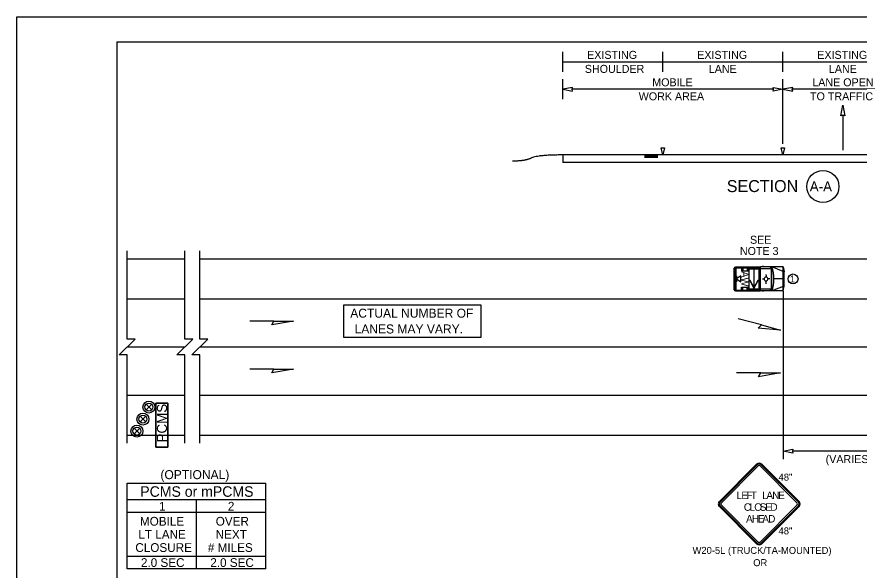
# Model space of a CAD drawing. Extents: x 0 to 17, y 0 to 11.
# Drawn here: x 0 to 8.42, y 5.47 to 11 of the extents above; entities that cross this region are included whole.
import ezdxf

# ---------------------------------------------------------------- set-up
doc = ezdxf.new("R2010")
doc.units = 0
for name, color, linetype in [('RD_ED_ShoulderPavedEdge', 7, 'Continuous'), ('RD_MK_LineEdgeWhite', 7, 'Continuous'), ('RD_MK_LineEdgeYellow', 7, 'Continuous'), ('RD_MK_LineLane', 7, 'Continuous'), ('SH_GI_PlotLimits', 7, 'Continuous'), ('SH_GI_SheetBorder3', 7, 'Continuous'), ('SH_TI_Tables', 7, 'Continuous'), ('SH_TI_WZSectionCut', 7, 'Continuous'), ('TR_SN_ConstructionSigns', 7, 'Continuous'), ('TR_WZ_ArrowLeftStrRightTurn', 7, 'Continuous'), ('TR_WZ_PCMS', 7, 'Continuous'), ('TR_WZ_PortableChangeMessageSign', 7, 'Continuous'), ('TR_WZ_PortableSignMountBlk-Org', 7, 'Continuous'), ('TR_WZ_ProtectiveVehicle', 7, 'Continuous'), ('TR_WZ_TrafficSafetyDrum', 7, 'Continuous'), ('TR_WZ_TransportableAttenuator', 7, 'Continuous'), ('TR_WZ_WorkZoneDetails', 7, 'Continuous'), ('TR_WZ_WorkZoneTextCurrent', 7, 'Continuous')]:
    doc.layers.add(name, color=color, linetype=linetype)

msp = doc.modelspace()

# ---------------------------------------------------------------- linework, layer by layer
at = {"layer": 'RD_ED_ShoulderPavedEdge'}
for p, q in [((1.1016, 8.5807), (1.6783, 8.5807)), ((1.8283, 8.5807), (16.62, 8.5807)), ((1.1016, 6.8207), (1.6783, 6.8207)), ((1.8283, 6.8207), (16.62, 6.8207))]:
    msp.add_line(p, q, dxfattribs=at)
at = {"layer": 'RD_MK_LineEdgeWhite'}
for p, q in [((1.1016, 7.2207), (1.6783, 7.2207)), ((1.8283, 7.2207), (16.62, 7.2207))]:
    msp.add_line(p, q, dxfattribs=at)
at = {"layer": 'RD_MK_LineEdgeYellow'}
for p, q in [((1.1016, 8.1807), (1.6783, 8.1807)), ((1.8283, 8.1807), (16.62, 8.1807))]:
    msp.add_line(p, q, dxfattribs=at)
at = {"layer": 'RD_MK_LineLane'}
for p, q in [((1.6783, 7.7007), (1.1016, 7.7007)), ((16.62, 7.7007), (1.8283, 7.7007))]:
    msp.add_line(p, q, dxfattribs=at)
at = {"layer": 'SH_GI_PlotLimits'}
msp.add_lwpolyline([(0, 11), (17, 11), (17, 0), (0, 0)], close=True, dxfattribs=at)
at = {"layer": 'SH_GI_SheetBorder3'}
for q in [(16.75, 10.75), (1, 0.25)]:
    msp.add_line((1, 10.75), q, dxfattribs=at)
at = {"layer": 'SH_TI_Tables'}
msp.add_lwpolyline([(3.266, 8.1232), (4.6358, 8.1232), (4.6358, 7.7968), (3.266, 7.7968)], close=True, dxfattribs=at)
at = {"layer": 'SH_TI_WZSectionCut'}
for p, q in [((5.4546, 10.45), (5.4546, 10.65)), ((6.4546, 10.45), (6.4546, 10.65)), ((7.6546, 10.45), (7.6546, 10.65)), ((5.4546, 10.55), (6.4546, 10.55)), ((6.4546, 10.55), (7.6546, 10.55)), ((7.6546, 10.55), (8.8546, 10.55)), ((5.4546, 10.176), (5.4546, 10.376)), ((7.6546, 9.7297), (7.6546, 10.376)), ((7.5609, 10.276), (5.5484, 10.276)), ((8.7609, 10.276), (7.7484, 10.276)), ((5.4546, 9.6199), (5.4546, 9.5449)), ((9.8546, 9.6199), (5.4546, 9.6199)), ((6.2716, 9.6147), (6.4046, 9.6147)), ((6.2716, 9.6091), (6.4046, 9.6091)), ((6.2716, 9.6034), (6.4046, 9.6034)), ((6.2716, 9.5982), (6.4046, 9.5982)), ((9.8546, 9.5449), (5.4546, 9.5449))]:
    msp.add_line(p, q, dxfattribs=at)
for points in [[(5.4546, 10.276), (5.5529, 10.2567), (5.5484, 10.276), (5.5529, 10.2953)], [(7.6546, 10.276), (7.5564, 10.2567), (7.5609, 10.276), (7.5564, 10.2953)], [(7.6546, 10.276), (7.7529, 10.2567), (7.7484, 10.276), (7.7529, 10.2953)], [(6.4379, 9.6897), (6.4713, 9.6897), (6.4546, 9.6199)], [(7.638, 9.6897), (7.6713, 9.6897), (7.6547, 9.6199)]]:
    msp.add_lwpolyline(points, close=True, dxfattribs=at)
msp.add_circle((8.055, 9.305), 0.16, dxfattribs=at)
msp.add_open_spline([(5.4546, 9.6199), (5.2035, 9.6199), (5.078, 9.5578), (4.9525, 9.5578)], degree=2, dxfattribs=at)
at = {"layer": 'TR_SN_ConstructionSigns'}
for p, q in [((7.3917, 6.5301), (7.0205, 6.1588)), ((7.3984, 6.5234), (7.0271, 6.1522)), ((7.0382, 6.1411), (7.4094, 6.5124)), ((7.4271, 6.5124), (7.7983, 6.1411)), ((7.8094, 6.1522), (7.4381, 6.5234)), ((7.816, 6.1588), (7.4448, 6.5301)), ((7.0205, 6.1058), (7.3917, 5.7345)), ((7.0271, 6.1124), (7.3984, 5.7412)), ((7.4094, 5.7522), (7.0382, 6.1235)), ((7.7983, 6.1235), (7.4271, 5.7522)), ((7.4381, 5.7412), (7.8094, 6.1124)), ((7.4448, 5.7345), (7.816, 6.1058))]:
    msp.add_line(p, q, dxfattribs=at)
for centre, radius, start, end in [((7.4183, 6.5036), 0.0375, 45, 135), ((7.4183, 6.5036), 0.0281, 45, 135), ((7.4183, 6.5036), 0.0125, 45, 135), ((7.047, 6.1323), 0.0375, 135, 225.00001), ((7.047, 6.1323), 0.0281, 135, 225.00001), ((7.7895, 6.1323), 0.0281, 315.00002, 45), ((7.7895, 6.1323), 0.0375, 315.00001, 45.00001), ((7.047, 6.1323), 0.0125, 135, 225.00001), ((7.7895, 6.1323), 0.0125, 315.00002, 45), ((7.4183, 5.7611), 0.0375, 225.00001, 315.00001), ((7.4183, 5.7611), 0.0281, 225.00001, 315.00002), ((7.4183, 5.7611), 0.0125, 225.00001, 315.00002)]:
    msp.add_arc(centre, radius, start, end, dxfattribs=at)
at = {"layer": 'TR_WZ_ArrowLeftStrRightTurn'}
msp.add_line((8.2546, 10.0168), (8.2546, 9.667), dxfattribs=at)
msp.add_lwpolyline([(8.2546, 10.117), (8.2752, 10.0119), (8.2546, 10.0168), (8.234, 10.0119)], close=True, dxfattribs=at)
at = {"layer": 'TR_WZ_PCMS'}
for points in [[(1.39, 7.1407), (1.51, 7.1407), (1.51, 6.7007), (1.39, 6.7007), (1.39, 7.1407)], [(1.39, 6.7007), (1.51, 6.7007), (1.51, 7.1407), (1.39, 7.1407), (1.39, 6.7007)]]:
    msp.add_lwpolyline(points, dxfattribs=at)
at = {"layer": 'TR_WZ_PortableChangeMessageSign'}
for p, q in [((1.1016, 6.3407), (2.4876, 6.3407)), ((1.1016, 5.4839), (1.1016, 6.3407)), ((2.4876, 5.4839), (2.4876, 6.3407)), ((2.4876, 6.1727), (1.1016, 6.1727)), ((1.7946, 5.4839), (1.7946, 6.1727)), ((1.7946, 6.0467), (1.1016, 6.0467)), ((2.4876, 6.0467), (1.7946, 6.0467)), ((1.1016, 5.6099), (1.7946, 5.6099)), ((1.7946, 5.6099), (2.4876, 5.6099)), ((2.4876, 5.4839), (1.1016, 5.4839))]:
    msp.add_line(p, q, dxfattribs=at)
at = {"layer": 'TR_WZ_PortableSignMountBlk-Org'}
msp.add_line((7.1919, 8.4107), (7.1919, 8.3507), dxfattribs=at)
msp.add_lwpolyline([(7.1919, 8.3807), (7.235, 8.3507), (7.235, 8.4107)], close=True, dxfattribs=at)
at = {"layer": 'TR_WZ_ProtectiveVehicle'}
for p, q in [((7.4611, 8.5041), (7.4475, 8.5041)), ((7.1685, 8.272), (7.1685, 8.4895)), ((7.1739, 8.4968), (7.1792, 8.4968)), ((7.1792, 8.2647), (7.1792, 8.4968)), ((7.18, 8.5007), (7.4269, 8.5007)), ((7.18, 8.2607), (7.18, 8.5007)), ((7.187, 8.2703), (7.187, 8.4912)), ((7.187, 8.4912), (7.4199, 8.4912)), ((7.2427, 8.4912), (7.2427, 8.4635)), ((7.2427, 8.4635), (7.3086, 8.4635)), ((7.2559, 8.4912), (7.2559, 8.4635)), ((7.2967, 8.4912), (7.2967, 8.4635)), ((7.3086, 8.4912), (7.3086, 8.4635)), ((7.4199, 8.2703), (7.4199, 8.4912)), ((7.4269, 8.2607), (7.4269, 8.5007)), ((7.4302, 8.2607), (7.4302, 8.5007)), ((7.6569, 8.5007), (7.4302, 8.5007)), ((7.5415, 8.4821), (7.4302, 8.4821)), ((7.4862, 8.4269), (7.4866, 8.4088)), ((7.5295, 8.4821), (7.5415, 8.5007)), ((7.5415, 8.2607), (7.5415, 8.5007)), ((7.5435, 8.2607), (7.5435, 8.5007)), ((7.6569, 8.4568), (7.5435, 8.5007)), ((7.6569, 8.2607), (7.6569, 8.5007)), ((7.6569, 8.5007), (7.668, 8.4523)), ((7.668, 8.3092), (7.668, 8.4523)), ((7.1685, 8.3976), (7.1792, 8.3931)), ((7.1685, 8.3638), (7.1792, 8.3683)), ((7.1714, 8.3807), (7.1763, 8.3807)), ((7.1739, 8.3773), (7.1739, 8.3841)), ((7.4501, 8.3816), (7.4679, 8.3812)), ((7.4702, 8.3811), (7.4702, 8.3811)), ((7.4871, 8.3332), (7.4871, 8.3525)), ((7.5233, 8.3806), (7.5081, 8.3806)), ((7.6569, 8.3807), (7.5658, 8.3807)), ((7.1739, 8.2647), (7.1792, 8.2647)), ((7.18, 8.2607), (7.4269, 8.2607)), ((7.187, 8.2703), (7.4199, 8.2703)), ((7.2427, 8.2979), (7.3086, 8.2979)), ((7.2427, 8.2703), (7.2427, 8.2979)), ((7.2559, 8.2703), (7.2559, 8.2979)), ((7.2967, 8.2703), (7.2967, 8.2979)), ((7.3086, 8.2703), (7.3086, 8.2979)), ((7.5415, 8.2793), (7.4302, 8.2793)), ((7.6569, 8.2607), (7.4302, 8.2607)), ((7.4611, 8.2573), (7.4475, 8.2573)), ((7.5415, 8.2607), (7.5271, 8.2793)), ((7.6569, 8.3047), (7.5435, 8.2607)), ((7.6569, 8.2607), (7.668, 8.3092))]:
    msp.add_line(p, q, dxfattribs=at)
for centre, major_axis, start_param, end_param in [((7.1739, 8.4895), (0, 0.00732), 0, 1.570796), ((7.3816, 8.3808), (0, 0.2518), 4.215667, 5.208926), ((7.1739, 8.272), (0, -0.00732), 4.712389, 6.283185)]:
    msp.add_ellipse(centre, major_axis=major_axis, ratio=0.73155, start_param=start_param, end_param=end_param, dxfattribs=at)
for centre, major_axis in [((7.1739, 8.3807), (0, -0.00338)), ((7.4871, 8.3807), (0, -0.0231))]:
    msp.add_ellipse(centre, major_axis=major_axis, ratio=0.73155, dxfattribs=at)
at = {"layer": 'TR_WZ_TrafficSafetyDrum'}
for p, q in [((1.2917, 7.129), (1.3483, 7.0724)), ((1.3483, 7.129), (1.2917, 7.0724)), ((1.2317, 7.009), (1.2883, 6.9524)), ((1.2883, 7.009), (1.2317, 6.9524)), ((1.1717, 6.889), (1.2283, 6.8324)), ((1.2283, 6.889), (1.1717, 6.8324))]:
    msp.add_line(p, q, dxfattribs=at)
for centre, radius in [((1.32, 7.1007), 0.06), ((1.32, 7.1007), 0.06), ((1.32, 7.1007), 0.04), ((1.26, 6.9807), 0.06), ((1.26, 6.9807), 0.06), ((1.26, 6.9807), 0.04), ((1.2, 6.8607), 0.06), ((1.2, 6.8607), 0.06), ((1.2, 6.8607), 0.04)]:
    msp.add_circle(centre, radius, dxfattribs=at)
at = {"layer": 'TR_WZ_TransportableAttenuator'}
for points in [[(7.3173, 8.4825), (7.4133, 8.4825), (7.4133, 8.2789), (7.3173, 8.2789)], [(7.3637, 8.4743), (7.3637, 8.2973), (7.3669, 8.2973), (7.3669, 8.4743)], [(7.3239, 8.3646), (7.3653, 8.2871), (7.3637, 8.2973), (7.3266, 8.3669)], [(7.3653, 8.2871), (7.4066, 8.3646), (7.4039, 8.3669), (7.3669, 8.2973)], [(7.3653, 8.2871), (7.3669, 8.2973), (7.3637, 8.2973)]]:
    msp.add_lwpolyline(points, close=True, dxfattribs=at)
at = {"layer": 'TR_WZ_WorkZoneDetails'}
for p, q in [((7.6569, 8.2607), (7.6569, 6.5811)), ((2.5694, 7.96), (2.3283, 7.96)), ((7.4398, 7.9214), (7.2069, 7.9838)), ((2.5694, 7.48), (2.3283, 7.48)), ((7.4331, 7.4414), (7.192, 7.4414)), ((9.5632, 6.6611), (7.7506, 6.6611))]:
    msp.add_line(p, q, dxfattribs=at)
for points in [[(1.1016, 6.7407), (1.1016, 7.6233), (1.0216, 7.6233), (1.1817, 7.7782), (1.1016, 7.7782), (1.1016, 8.6607)], [(1.6783, 6.7407), (1.6783, 7.6233), (1.5983, 7.6233), (1.7583, 7.7782), (1.6783, 7.7782), (1.6783, 8.6607)], [(1.8283, 6.7407), (1.8283, 7.6233), (1.7483, 7.6233), (1.9083, 7.7782), (1.8283, 7.7782), (1.8283, 8.6607)]]:
    msp.add_lwpolyline(points, dxfattribs=at)
for points in [[(2.766, 7.96), (2.5471, 7.9214), (2.5694, 7.96)], [(7.6296, 7.8706), (7.4083, 7.89), (7.4398, 7.9214)], [(2.766, 7.48), (2.5471, 7.4414), (2.5694, 7.48)], [(7.6296, 7.4414), (7.4108, 7.4029), (7.4331, 7.4414)], [(7.6569, 6.6611), (7.7552, 6.6803), (7.7506, 6.6611), (7.7552, 6.6418)]]:
    msp.add_lwpolyline(points, close=True, dxfattribs=at)
msp.add_circle((7.7561, 8.3807), 0.05, dxfattribs=at)

# ---------------------------------------------------------------- texts
at = {"layer": 'SH_TI_Tables'}
for s, p in [('ACTUAL NUMBER OF', (3.3317, 7.9938)), ('LANES MAY VARY.', (3.375, 7.8363))]:
    msp.add_text(s, height=0.09, rotation=360, dxfattribs=at).set_placement(p)
at = {"layer": 'SH_TI_WZSectionCut'}
for s, height, p in [('EXISTING', 0.08, (5.6986, 10.58)), ('EXISTING', 0.08, (6.7986, 10.58)), ('EXISTING', 0.08, (7.9986, 10.58)), ('SHOULDER', 0.08, (5.6757, 10.44)), ('LANE', 0.08, (6.9145, 10.44)), ('LANE', 0.08, (8.1145, 10.44)), ('SECTION', 0.12, (7.0943, 9.2489)), ('A-A', 0.1, (7.9231, 9.255))]:
    msp.add_text(s, height=height, rotation=360, dxfattribs=at).set_placement(p)
for s, p in [('MOBILE', (6.3496, 10.306)), ('LANE OPEN', (7.9489, 10.306)), ('WORK AREA', (6.2142, 10.166)), ('TO TRAFFIC', (7.9261, 10.166))]:
    msp.add_text(s, height=0.08, dxfattribs=at).set_placement(p)
at = {"layer": 'TR_SN_ConstructionSigns'}
for s, height, p in [('48"', 0.07, (7.6119, 6.366)), ('L', 0.075, (7.1914, 6.1815)), ('E', 0.075, (7.2401, 6.1815)), ('F', 0.075, (7.2911, 6.1815)), ('T', 0.075, (7.3339, 6.1815)), ('L', 0.075, (7.4471, 6.1815)), ('A', 0.075, (7.4899, 6.1815)), ('N', 0.075, (7.5484, 6.1815)), ('E', 0.075, (7.6069, 6.1815)), ('C', 0.075, (7.2645, 6.0643)), ('L', 0.075, (7.3215, 6.0643)), ('O', 0.075, (7.3688, 6.0643)), ('S', 0.075, (7.4243, 6.0643)), ('E', 0.075, (7.479, 6.0643)), ('D', 0.075, (7.53, 6.0643)), ('A', 0.075, (7.287, 5.9471)), ('H', 0.075, (7.3455, 5.9471)), ('E', 0.075, (7.404, 5.9471)), ('A', 0.075, (7.449, 5.9471)), ('D', 0.075, (7.5075, 5.9471)), ('48"', 0.07, (7.6119, 5.8286)), ('W20-5L (TRUCK/TA-MOUNTED)', 0.07, (6.7522, 5.6336)), ('OR', 0.07, (7.3584, 5.5111))]:
    msp.add_text(s, height=height, dxfattribs=at).set_placement(p)
at = {"layer": 'TR_WZ_PCMS'}
msp.add_text('PCMS', height=0.1, rotation=90, dxfattribs=at).set_placement((1.5, 6.7471))
at = {"layer": 'TR_WZ_PortableChangeMessageSign'}
for s, height, p in [('PCMS or mPCMS', 0.105, (1.2335, 6.2042)), ('1', 0.0875, (1.4208, 6.066)), ('2', 0.0875, (2.1087, 6.066)), ('MOBILE', 0.0875, (1.2299, 5.9158)), ('OVER', 0.0875, (1.9874, 5.9158)), (' LT LANE', 0.0875, (1.182, 5.7846)), ('NEXT', 0.0875, (1.9866, 5.7846)), ('CLOSURE', 0.0875, (1.184, 5.6533)), ('# MILES', 0.0875, (1.9088, 5.6533)), ('2.0 SEC', 0.0875, (1.2399, 5.5032)), ('2.0 SEC', 0.0875, (1.9329, 5.5032))]:
    msp.add_text(s, height=height, rotation=360, dxfattribs=at).set_placement(p)
at = {"layer": 'TR_WZ_ProtectiveVehicle'}
msp.add_text('AW', height=0.07, rotation=270, dxfattribs=at).set_placement((7.2407, 8.4574))
at = {"layer": 'TR_WZ_WorkZoneDetails'}
for s, height, p in [('1', 0.07, (7.725, 8.3457)), ('(OPTIONAL)', 0.09, (1.4346, 6.3807))]:
    msp.add_text(s, height=height, dxfattribs=at).set_placement(p)
at = {"layer": 'TR_WZ_WorkZoneTextCurrent'}
for s, p in [('SEE', (7.3262, 8.7324)), ('NOTE 3', (7.2252, 8.6204)), ('(VARIES, SEE NOTE 4)', (8.0822, 6.5411))]:
    msp.add_text(s, height=0.08, dxfattribs=at).set_placement(p)

doc.saveas('drawing.dxf')
